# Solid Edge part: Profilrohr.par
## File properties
Username: bmolnar
Dokumentum tartalom típus: 0
Author: bmolnar
Last saved by: bmolnar
Revision: 83
Sűrűség: 0,000 kg/m^3
Pontosság: 0,990
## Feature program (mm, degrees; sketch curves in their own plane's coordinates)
base feature "unnamed BaseFeature 1"
thread "unnamed Thread 1"
thread "Menet_2"  ThreadDepth = 3.9 mm
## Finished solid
Body 1: solid body, 69 faces, 145 edges, 89 vertices.
  Faces by surface: plane 38, cylinder 24, cone 6, torus 1
  Edges by curve: line 77, circle 53, curve on surface 10, ellipse 4, intersection 1
Bounding box of the edges (mm; curved faces can reach further): 25.000 x 25.000 x 67.000, from (-12.5, -12.5, 0) to (12.5, 12.5, 67).
Cylindrical faces by radius (mm): R0.433 x1, R0.5 x2, R1.5 x1, R1.8 x6, R1.9 x2, R2.067 x4, R2.8 x4, R6 x1, R6.85 x1, R6.95 x1, R7.3 x1
Conical faces (half-angle, radius in mm at the cone's reference point): 30 deg R6.225 x1, 30 deg R6.9943 x1, 30 deg R7.0943 x1, 45 deg R2.217 x2, 45 deg R4.45 x1
Toroidal faces (ring radius, tube radius in mm): R5.6 r0.4 x1
Planar faces by outward normal: +x 3, +y 7, +z 7, -x 3, -y 6, -z 4, oblique 8
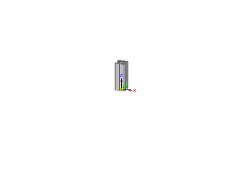
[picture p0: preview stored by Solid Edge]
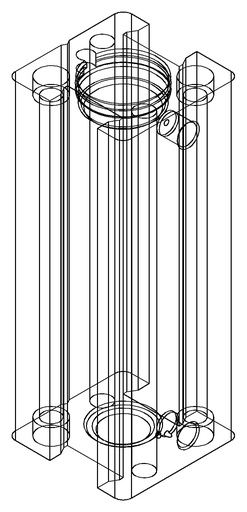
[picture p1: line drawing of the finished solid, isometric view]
